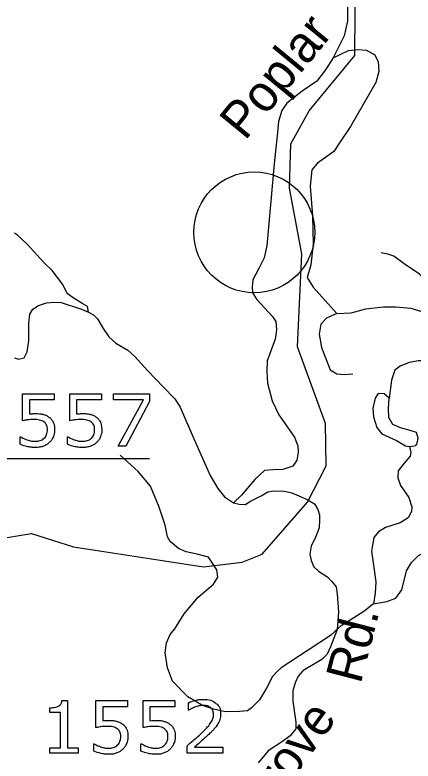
# Model space of a CAD drawing. Extents: x 1190067 to 1192950, y 891516 to 893460.
# Drawn here: x 1191019.1 to 1191052.1, y 893093.4 to 893155.2 of the extents above; entities that cross this region are included whole.
import ezdxf

# ---------------------------------------------------------------- set-up
doc = ezdxf.new("R2010")
doc.units = 0
doc.layers.add('Default', color=7, linetype='Continuous')
doc.layers.add('Prop DSN Text', color=7, linetype='Continuous')

msp = doc.modelspace()

# ---------------------------------------------------------------- linework, layer by layer
at = {"layer": 'Default'}
msp.add_line((1191015.129, 893118.462), (1191030.27, 893118.462), dxfattribs=at)
for points in [[(1191015.07, 893111.382), (1191020.495, 893112.252), (1191023.978, 893111.147), (1191034.723, 893109.495), (1191037.943, 893109.893), (1191039.57, 893110.547), (1191043.333, 893114.838), (1191044.873, 893117.853), (1191044.82, 893121.357), (1191042.51, 893127.723), (1191042.878, 893135.415), (1191041.845, 893140.834), (1191041.95, 893144.509), (1191043.473, 893147.236), (1191047.253, 893151.814), (1191047.305, 893159.11)], [(1191046.64, 893155.814), (1191046.628, 893154.663), (1191046.352, 893153.465), (1191045.463, 893151.627), (1191044.834, 893150.633), (1191044.097, 893149.712), (1191042.889, 893148.883), (1191041.624, 893147.87), (1191041.21, 893147.272), (1191040.934, 893146.374), (1191040.842, 893145.453), (1191040.565, 893142.851), (1191039.979, 893136.058), (1191039.76, 893135.068), (1191039.3, 893134.193), (1191038.817, 893133.249), (1191038.748, 893132.651), (1191038.794, 893132.167), (1191039.139, 893131.615), (1191040.427, 893130.233), (1191040.715, 893129.796), (1191040.761, 893129.128), (1191040.646, 893128.345), (1191040.002, 893126.549), (1191039.956, 893125.697), (1191040.025, 893124.707), (1191040.404, 893123.233), (1191040.957, 893122.082), (1191042.245, 893120.24), (1191042.544, 893119.526), (1191042.567, 893118.997), (1191042.452, 893118.329), (1191042.13, 893117.823), (1191041.29, 893117.546), (1191040.462, 893117.523), (1191039.772, 893117.477), (1191038.989, 893116.74), (1191037.885, 893115.428), (1191037.218, 893114.806)], [(1191045.463, 893151.627), (1191046.038, 893151.896), (1191046.73, 893152.242), (1191047.497, 893152.319), (1191048.188, 893152.28), (1191048.88, 893151.896), (1191049.187, 893151.32), (1191049.225, 893150.513), (1191048.995, 893149.591), (1191046.883, 893145.941), (1191046.038, 893144.673), (1191045.501, 893143.866), (1191044.157, 893142.906), (1191043.696, 893142.368), (1191043.543, 893141.023), (1191043.735, 893138.564), (1191043.812, 893136.221), (1191043.62, 893134.492), (1191043.313, 893133.454), (1191043.792, 893132.648), (1191045.751, 893130.458)], [(1191025.232, 893130.567), (1191025.137, 893131.062), (1191024.758, 893131.283), (1191023.939, 893131.755), (1191023.467, 893132.134), (1191023.089, 893132.859), (1191022.206, 893134.026), (1191021.513, 893134.688), (1191020.158, 893136.201), (1191019.339, 893136.958), (1191019.087, 893137.115)], [(1191054.312, 893129.997), (1191054.427, 893131.264), (1191054.351, 893132.033), (1191053.621, 893132.763), (1191052.584, 893133.723), (1191051.318, 893134.569), (1191050.473, 893135.222), (1191049.974, 893135.375), (1191049.436, 893135.491)], [(1191019.113, 893126.808), (1191019.444, 893126.698), (1191019.911, 893126.808), (1191020.159, 893127.304), (1191020.296, 893128.212), (1191020.296, 893129.644), (1191020.379, 893130.415), (1191020.627, 893130.827), (1191021.094, 893131.13), (1191021.755, 893131.351), (1191022.387, 893131.406), (1191022.965, 893131.378), (1191024.643, 893130.827), (1191025.232, 893130.567)], [(1191045.751, 893130.458), (1191046.941, 893130.535), (1191048.169, 893130.842), (1191049.628, 893131.034), (1191050.626, 893131.034), (1191051.893, 893130.919), (1191053.237, 893130.496), (1191054.312, 893129.997), (1191055.349, 893129.497), (1191056.001, 893129.228), (1191056.232, 893128.959)], [(1191025.232, 893130.567), (1191025.637, 893130.364), (1191025.961, 893130.04), (1191026.427, 893129.229), (1191026.893, 893128.54), (1191027.47, 893128.013), (1191028.462, 893127.446), (1191029.05, 893126.919), (1191030.123, 893125.723), (1191031.399, 893124.385), (1191032.371, 893123.392), (1191032.807, 893122.703), (1191033.961, 893120.027), (1191035.278, 893117.068), (1191035.926, 893115.974), (1191036.473, 893115.305), (1191037.218, 893114.806)], [(1191045.751, 893130.458), (1191044.906, 893130.073), (1191044.445, 893129.574), (1191044.292, 893128.767), (1191044.484, 893127.653), (1191045.213, 893125.809), (1191045.751, 893125.463), (1191046.365, 893125.425), (1191047.094, 893125.463)], [(1191056.232, 893128.959), (1191056.001, 893127.922), (1191055.003, 893126.693), (1191054.696, 893126.539), (1191054.082, 893126.424), (1191053.276, 893126.539), (1191052.508, 893126.539), (1191051.74, 893126.424), (1191051.01, 893126.116), (1191050.55, 893125.77), (1191050.281, 893124.964), (1191050.089, 893123.465)], [(1191019.769, 893121.587), (1191019.769, 893123.827), (1191022.386, 893123.827), (1191022.386, 893123.316), (1191020.33, 893123.316), (1191020.33, 893122.16)], [(1191023.674, 893121.587), (1191023.674, 893123.827), (1191026.291, 893123.827), (1191026.291, 893123.316), (1191024.235, 893123.316), (1191024.235, 893122.16)], [(1191030.27, 893123.177), (1191028.305, 893119.477), (1191027.678, 893119.477), (1191029.766, 893123.316), (1191027.294, 893123.316), (1191027.294, 893123.827), (1191030.27, 893123.827), (1191030.27, 893123.177)], [(1191050.089, 893123.465), (1191049.686, 893123.811), (1191049.187, 893123.849), (1191048.918, 893123.465), (1191048.726, 893122.62), (1191048.803, 893121.928), (1191049.072, 893121.045), (1191049.494, 893120.507), (1191050.684, 893119.969), (1191051.452, 893119.508), (1191051.759, 893119.47)], [(1191051.759, 893119.47), (1191052.297, 893119.546), (1191052.412, 893119.739), (1191052.489, 893120.161), (1191052.335, 893120.622), (1191051.836, 893120.776), (1191051.03, 893121.006), (1191050.377, 893121.275), (1191050.07, 893121.852), (1191050.031, 893122.62), (1191050.089, 893123.465)], [(1191019.581, 893119.639), (1191019.581, 893120.255), (1191019.622, 893120.255)], [(1191023.485, 893119.639), (1191023.485, 893120.255), (1191023.526, 893120.255)], [(1191051.759, 893119.47), (1191051.874, 893118.97), (1191051.836, 893118.663), (1191051.337, 893118.087), (1191050.838, 893117.433), (1191050.799, 893116.857), (1191051.03, 893116.242), (1191051.721, 893115.243), (1191051.97, 893114.475), (1191051.932, 893114.091), (1191051.663, 893113.553), (1191051.01, 893113.13), (1191049.782, 893112.746), (1191049.206, 893112.4), (1191048.822, 893111.939), (1191048.707, 893111.286), (1191048.63, 893110.787), (1191048.822, 893109.442), (1191048.976, 893108.251), (1191048.937, 893107.329), (1191048.803, 893106.445)], [(1191045.24, 893103.805), (1191043.389, 893102.603), (1191041.163, 893101.143), (1191040.817, 893100.836), (1191040.433, 893100.413), (1191039.934, 893099.453), (1191039.358, 893098.492), (1191038.705, 893097.839), (1191038.36, 893097.57), (1191037.707, 893097.532), (1191036.555, 893097.494), (1191035.557, 893097.724), (1191034.636, 893098.031), (1191033.446, 893098.723), (1191032.179, 893100.029), (1191031.756, 893101.143), (1191031.564, 893102.373), (1191031.68, 893103.218), (1191031.987, 893103.91), (1191032.371, 893104.371), (1191033.138, 893105.6), (1191034.29, 893106.983), (1191035.557, 893108.059), (1191035.903, 893108.635), (1191035.826, 893109.25), (1191035.135, 893110.287), (1191034.194, 893110.556), (1191033.311, 893110.748), (1191032.659, 893111.017), (1191031.987, 893111.594), (1191031.756, 893111.978), (1191031.564, 893112.938), (1191031.065, 893114.437), (1191030.336, 893116.166), (1191029.338, 893117.395), (1191027.84, 893118.74)], [(1191037.218, 893114.806), (1191037.678, 893114.691), (1191038.207, 893114.668), (1191038.552, 893114.898), (1191039.496, 893115.382), (1191040.048, 893115.704), (1191040.531, 893115.796), (1191041.428, 893115.75), (1191042.027, 893115.612), (1191042.625, 893115.382), (1191043.292, 893115.06), (1191043.913, 893114.714), (1191044.189, 893114.254), (1191044.327, 893113.793), (1191044.327, 893113.402), (1191044.304, 893112.734), (1191044.017, 893112.02), (1191043.649, 893111.214), (1191043.534, 893110.547), (1191043.626, 893110.017), (1191043.856, 893109.511), (1191044.247, 893109.142), (1191044.937, 893108.705), (1191045.351, 893108.29), (1191045.697, 893107.83), (1191045.789, 893107.231), (1191045.892, 893105.757), (1191045.777, 893104.307), (1191045.225, 893102.879), (1191044.949, 893102.258), (1191044.512, 893101.82), (1191042.958, 893100.876), (1191042.567, 893100.439), (1191042.314, 893099.909), (1191042.107, 893099.241), (1191042.13, 893098.389), (1191042.268, 893097.422), (1191042.36, 893096.64), (1191042.36, 893096.087), (1191041.9, 893095.511), (1191041.256, 893095.028), (1191040.071, 893094.268), (1191039.68, 893093.807), (1191039.266, 893093.278)], [(1191048.803, 893106.445), (1191049.897, 893106.637), (1191050.626, 893106.906), (1191051.126, 893107.598), (1191051.509, 893109.173), (1191051.932, 893109.865), (1191052.508, 893110.441), (1191053.583, 893110.979), (1191054.965, 893111.44), (1191056.309, 893111.632)], [(1191048.803, 893106.445), (1191047.997, 893105.792), (1191046.038, 893104.563), (1191045.24, 893103.805)], [(1191023.023, 893098.441), (1191023.476, 893098.441), (1191023.476, 893094.521), (1191024.364, 893094.521), (1191024.364, 893094.077)], [(1191025.836, 893096.186), (1191025.836, 893098.427), (1191028.453, 893098.427), (1191028.453, 893097.916), (1191026.397, 893097.916), (1191026.397, 893096.76)], [(1191029.741, 893096.186), (1191029.741, 893098.427), (1191032.358, 893098.427), (1191032.358, 893097.916), (1191030.302, 893097.916), (1191030.302, 893096.76)], [(1191033.515, 893097.635), (1191033.486, 893097.635), (1191033.486, 893098.248)], [(1191024.364, 893094.077), (1191022.01, 893094.077), (1191022.01, 893094.521), (1191022.915, 893094.521), (1191022.915, 893097.436), (1191022.01, 893097.436), (1191022.01, 893097.834)], [(1191025.648, 893094.239), (1191025.648, 893094.855), (1191025.689, 893094.855)], [(1191029.553, 893094.239), (1191029.553, 893094.855), (1191029.593, 893094.855)], [(1191036.326, 893094.077), (1191033.379, 893094.077), (1191033.379, 893094.692)], [(1191033.984, 893094.581), (1191036.326, 893094.581), (1191036.326, 893094.077)]]:
    msp.add_lwpolyline(points, dxfattribs=at)
for points in [[(1191020.33, 893122.16), (1191020.456, 893122.171), (1191020.587, 893122.177), (1191020.719, 893122.183), (1191020.815, 893122.183), (1191021.169, 893122.183), (1191021.435, 893122.123), (1191021.701, 893122.063), (1191021.923, 893121.911), (1191022.157, 893121.75), (1191022.286, 893121.496), (1191022.414, 893121.242), (1191022.414, 893120.859)], [(1191024.235, 893122.16), (1191024.36, 893122.171), (1191024.492, 893122.177), (1191024.623, 893122.183), (1191024.72, 893122.183), (1191025.074, 893122.183), (1191025.34, 893122.123), (1191025.606, 893122.063), (1191025.828, 893121.911), (1191026.062, 893121.75), (1191026.19, 893121.496), (1191026.319, 893121.242), (1191026.319, 893120.859)], [(1191019.622, 893120.255), (1191019.861, 893120.103), (1191020.182, 893119.996), (1191020.504, 893119.889), (1191020.813, 893119.889), (1191021.021, 893119.889), (1191021.215, 893119.948), (1191021.409, 893120.006), (1191021.561, 893120.153), (1191021.69, 893120.279), (1191021.756, 893120.454), (1191021.821, 893120.63), (1191021.821, 893120.861), (1191021.821, 893121.087), (1191021.744, 893121.242), (1191021.667, 893121.397), (1191021.529, 893121.491), (1191021.378, 893121.602), (1191021.16, 893121.648), (1191020.943, 893121.693), (1191020.674, 893121.693), (1191020.417, 893121.693), (1191020.179, 893121.658), (1191019.941, 893121.622), (1191019.769, 893121.587)], [(1191023.526, 893120.255), (1191023.766, 893120.103), (1191024.087, 893119.996), (1191024.408, 893119.889), (1191024.718, 893119.889), (1191024.926, 893119.889), (1191025.12, 893119.948), (1191025.314, 893120.006), (1191025.466, 893120.153), (1191025.595, 893120.279), (1191025.66, 893120.454), (1191025.726, 893120.63), (1191025.726, 893120.861), (1191025.726, 893121.087), (1191025.649, 893121.242), (1191025.571, 893121.397), (1191025.434, 893121.491), (1191025.282, 893121.602), (1191025.065, 893121.648), (1191024.847, 893121.693), (1191024.579, 893121.693), (1191024.322, 893121.693), (1191024.084, 893121.658), (1191023.846, 893121.622), (1191023.674, 893121.587)], [(1191022.414, 893120.859), (1191022.414, 893120.554), (1191022.303, 893120.277), (1191022.192, 893119.999), (1191022, 893119.809), (1191021.789, 893119.604), (1191021.499, 893119.495), (1191021.208, 893119.385), (1191020.825, 893119.385), (1191020.469, 893119.385), (1191020.139, 893119.459), (1191019.809, 893119.534), (1191019.581, 893119.639)], [(1191026.319, 893120.859), (1191026.319, 893120.554), (1191026.208, 893120.277), (1191026.097, 893119.999), (1191025.904, 893119.809), (1191025.694, 893119.604), (1191025.403, 893119.495), (1191025.113, 893119.385), (1191024.73, 893119.385), (1191024.373, 893119.385), (1191024.043, 893119.459), (1191023.713, 893119.534), (1191023.485, 893119.639)], [(1191022.01, 893097.834), (1191022.194, 893097.834), (1191022.404, 893097.865), (1191022.614, 893097.895), (1191022.722, 893097.954), (1191022.857, 893098.027), (1191022.934, 893098.139), (1191023.012, 893098.252), (1191023.023, 893098.441)], [(1191033.486, 893098.248), (1191033.693, 893098.35), (1191034.04, 893098.435), (1191034.387, 893098.519), (1191034.711, 893098.519), (1191035.381, 893098.519), (1191035.761, 893098.197), (1191036.142, 893097.874), (1191036.142, 893097.323), (1191036.142, 893097.074), (1191036.079, 893096.86), (1191036.016, 893096.645), (1191035.893, 893096.453), (1191035.779, 893096.272), (1191035.626, 893096.097), (1191035.472, 893095.921), (1191035.253, 893095.708), (1191034.94, 893095.402), (1191034.607, 893095.114), (1191034.274, 893094.827), (1191033.984, 893094.581)], [(1191033.379, 893094.692), (1191033.687, 893094.955), (1191033.995, 893095.218), (1191034.304, 893095.481), (1191034.571, 893095.741), (1191035.133, 893096.284), (1191035.341, 893096.604), (1191035.549, 893096.923), (1191035.549, 893097.294), (1191035.549, 893097.633), (1191035.325, 893097.824), (1191035.1, 893098.015), (1191034.699, 893098.015), (1191034.432, 893098.015), (1191034.122, 893097.922), (1191033.811, 893097.828), (1191033.515, 893097.635)], [(1191026.397, 893096.76), (1191026.523, 893096.771), (1191026.654, 893096.777), (1191026.786, 893096.783), (1191026.883, 893096.783), (1191027.236, 893096.783), (1191027.502, 893096.723), (1191027.768, 893096.663), (1191027.99, 893096.511), (1191028.224, 893096.35), (1191028.353, 893096.096), (1191028.482, 893095.842), (1191028.482, 893095.459)], [(1191030.302, 893096.76), (1191030.428, 893096.771), (1191030.559, 893096.777), (1191030.691, 893096.783), (1191030.787, 893096.783), (1191031.141, 893096.783), (1191031.407, 893096.723), (1191031.673, 893096.663), (1191031.895, 893096.511), (1191032.129, 893096.35), (1191032.258, 893096.096), (1191032.386, 893095.842), (1191032.386, 893095.459)], [(1191025.689, 893094.855), (1191025.928, 893094.703), (1191026.25, 893094.596), (1191026.571, 893094.489), (1191026.881, 893094.489), (1191027.088, 893094.489), (1191027.282, 893094.548), (1191027.477, 893094.606), (1191027.629, 893094.753), (1191027.757, 893094.879), (1191027.823, 893095.054), (1191027.889, 893095.23), (1191027.889, 893095.461), (1191027.889, 893095.687), (1191027.811, 893095.842), (1191027.734, 893095.997), (1191027.597, 893096.091), (1191027.445, 893096.202), (1191027.227, 893096.248), (1191027.01, 893096.293), (1191026.741, 893096.293), (1191026.484, 893096.293), (1191026.246, 893096.257), (1191026.008, 893096.222), (1191025.836, 893096.186)], [(1191029.593, 893094.855), (1191029.833, 893094.703), (1191030.154, 893094.596), (1191030.476, 893094.489), (1191030.785, 893094.489), (1191030.993, 893094.489), (1191031.187, 893094.548), (1191031.381, 893094.606), (1191031.533, 893094.753), (1191031.662, 893094.879), (1191031.728, 893095.054), (1191031.793, 893095.23), (1191031.793, 893095.461), (1191031.793, 893095.687), (1191031.716, 893095.842), (1191031.639, 893095.997), (1191031.501, 893096.091), (1191031.35, 893096.202), (1191031.132, 893096.248), (1191030.914, 893096.293), (1191030.646, 893096.293), (1191030.389, 893096.293), (1191030.151, 893096.257), (1191029.913, 893096.222), (1191029.741, 893096.186)], [(1191028.482, 893095.459), (1191028.482, 893095.154), (1191028.371, 893094.877), (1191028.26, 893094.599), (1191028.067, 893094.409), (1191027.857, 893094.204), (1191027.566, 893094.094), (1191027.275, 893093.985), (1191026.892, 893093.985), (1191026.536, 893093.985), (1191026.206, 893094.059), (1191025.876, 893094.134), (1191025.648, 893094.239)], [(1191032.386, 893095.459), (1191032.386, 893095.154), (1191032.275, 893094.877), (1191032.164, 893094.599), (1191031.971, 893094.409), (1191031.761, 893094.204), (1191031.47, 893094.094), (1191031.18, 893093.985), (1191030.797, 893093.985), (1191030.441, 893093.985), (1191030.111, 893094.059), (1191029.78, 893094.134), (1191029.553, 893094.239)]]:
    msp.add_open_spline(points, degree=3, dxfattribs=at)
at = {"layer": 'Prop DSN Text'}
msp.add_circle((1191038.931, 893137.187), 5, dxfattribs=at)
msp.add_circle((1191038.931, 893137.187), 5, dxfattribs=at)

# ---------------------------------------------------------------- texts
at = {"layer": 'Default'}
for s, rotation, p in [('Poplar', 50.58773, (1191038.159, 893144.711)), ('Rd.', 75.42543, (1191047.719, 893099.722)), ('Grove', 53.88028, (1191039.39, 893088.13))]:
    msp.add_text(s, height=3, rotation=rotation, dxfattribs=at).set_placement(p)

doc.saveas('drawing.dxf')
